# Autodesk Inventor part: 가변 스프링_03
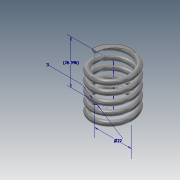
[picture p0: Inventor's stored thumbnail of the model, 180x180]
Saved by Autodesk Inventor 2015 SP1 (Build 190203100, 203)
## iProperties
Created: 2015-05
Part Number: 가변 스프링_03
Material: 강철, 탄소
Document SubType Name: Modeling
Designer: jckim
Density: 7.85 g/cm^3
Appearance: 반연마
Mass: 18.7154 g
Surface Area: 32.415 cm^2
Volume: 2.38413 cm^3
Author: jckim
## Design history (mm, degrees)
sketch "스케치1"
  geometry: L1 (0, 0)-(11, 0); L2 (11, 0)-(11, 26.346); L3 (11, 26.346)-(0, 26.346); L4 (0, 26.346)-(0, 0); C1 r 1.5 at (11, 0)
  constraints: 8 end point, 2 parallel, 1 centre point, 1 coincident, 1 horizontal, 1 perpendicular
  dimensions: "d0" = 3 diameter of C1; "d1" = 22 diameter of L2 L4; "d3" = 26.34571 distance of L1.end L2.end (derived)
feature "코일1" pitch "d4" = 10; turns "d6" = 5; dims "d5" = 26.34571 (= d3), "d7" = 0, angle "d8" = 90 deg, angle "d9" = 90 deg, "d10" = 0, "d11" = 0
sketch "스케치2"
  geometry: L1 (-12.5, 0)-(-9.5, 0) reference; 1 further point
  constraints: 1 horizontal alignment
extrude "돌출1" cut sketch "스케치2" stored distance "d12" = 10; taper "d13" = 0 deg
node "작업 평면1"
sketch "스케치3"
  geometry: L1 (1.5, 0)-(-1.5, 0) reference; 1 further point
  constraints: 1 horizontal alignment
extrude "돌출2" cut sketch "스케치3" stored distance "d15" = 10; taper "d16" = 0 deg
node "솔리드1"
node "절단 모서리 투영1"
node "절단 모서리 투영2"
other parameters: "d14" = 0
